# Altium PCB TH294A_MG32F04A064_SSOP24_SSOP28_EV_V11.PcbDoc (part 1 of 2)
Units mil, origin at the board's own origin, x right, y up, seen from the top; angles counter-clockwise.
Board outline 4724.41 x 2637.8 mil, 2 copper layers (Top Layer, Bottom Layer); 130 components, 100 nets, 562 pads, 309 vias.
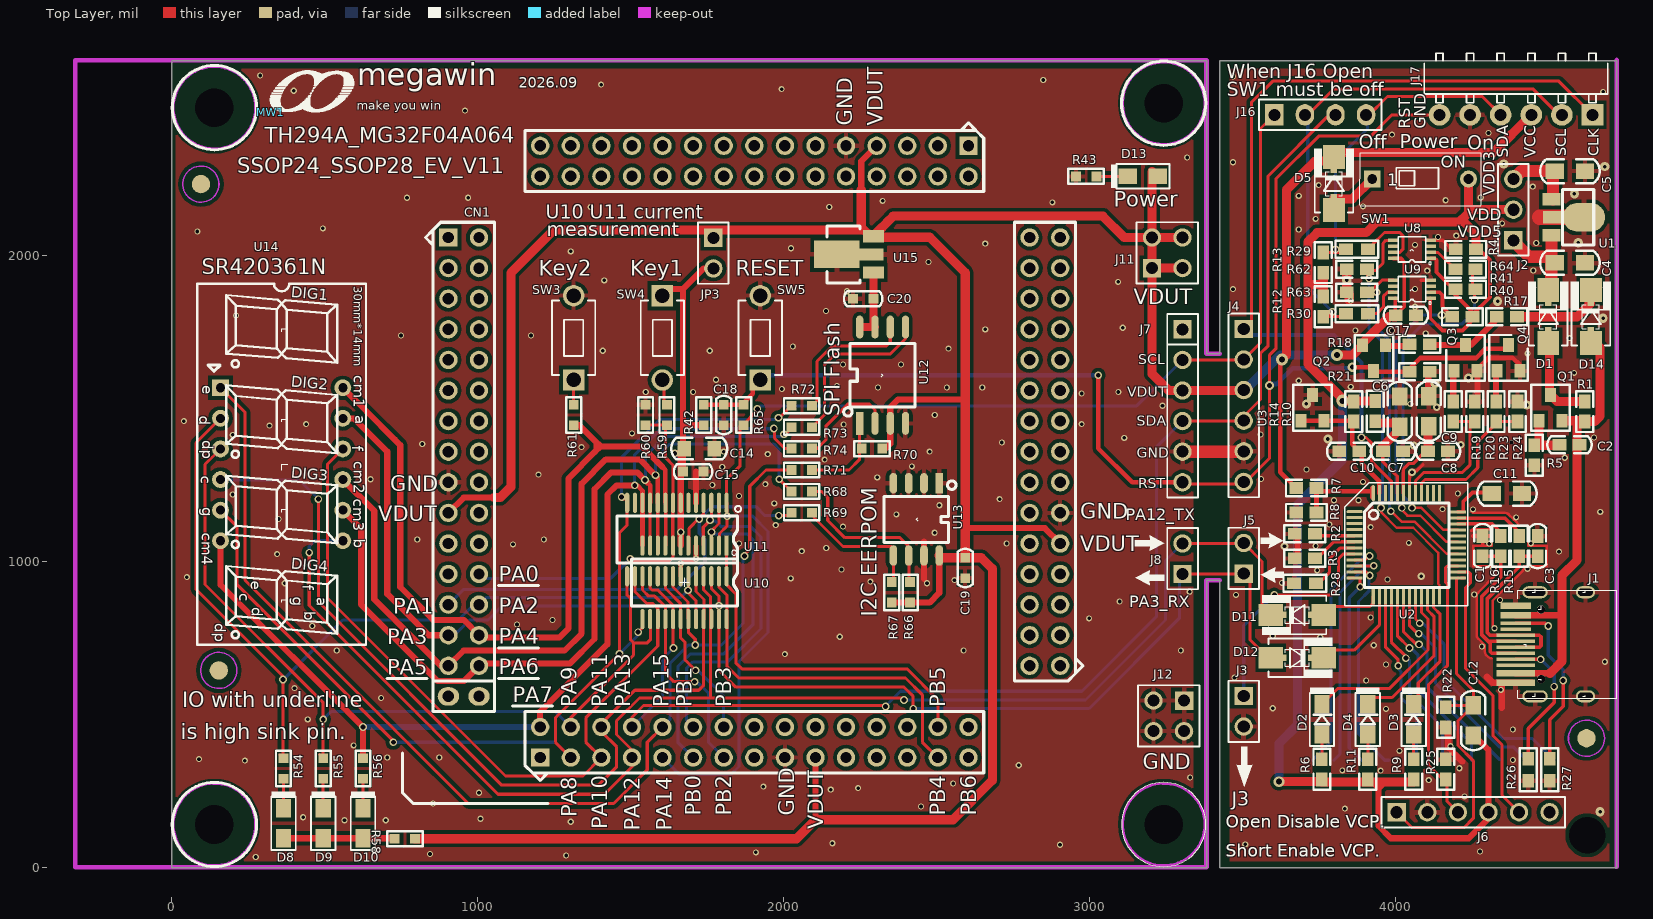
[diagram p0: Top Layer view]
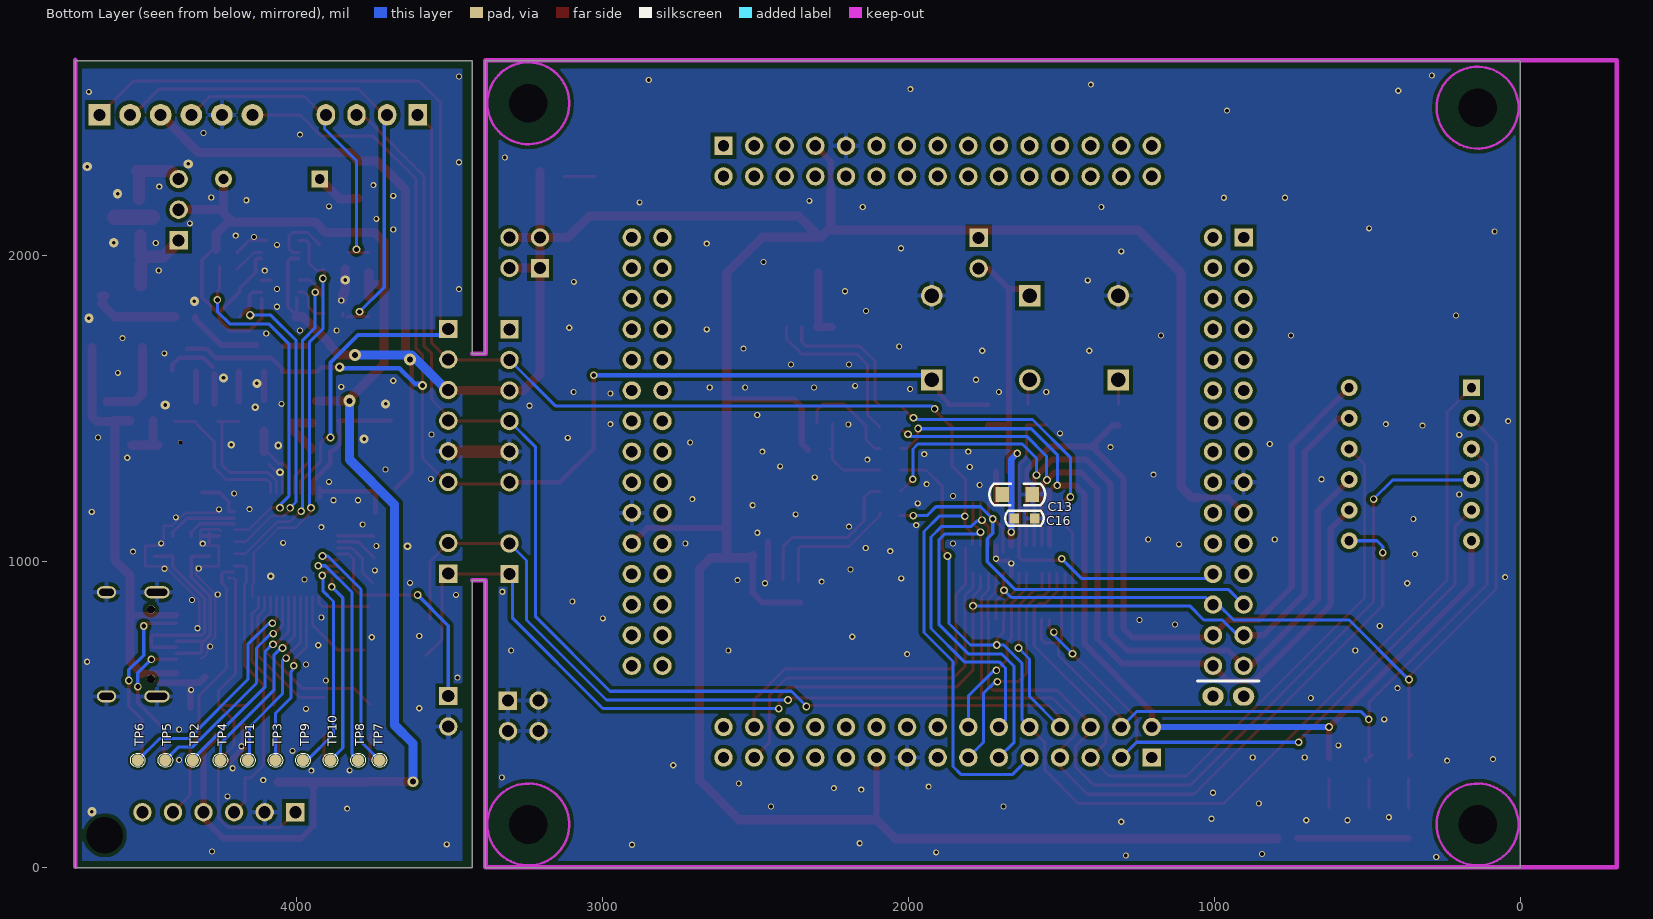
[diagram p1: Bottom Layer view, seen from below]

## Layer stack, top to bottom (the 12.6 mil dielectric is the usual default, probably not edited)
Top Layer: signal copper 1.4
Dielectric: dielectric 12.6, FR-4, Dk 4.8
Bottom Layer: signal copper 1.4

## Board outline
0,0 0,2637.8 3383.31,2637.8 3383.31,1680 3426.61,1680 3426.61,2637.8 4724.41,2637.8 4724.41,0 3426.61,0 3426.61,940 3383.31,940 3383.31,0

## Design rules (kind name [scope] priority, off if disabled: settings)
Clearance 12 [All] p1 off: gap=12
Clearance 7 [All] p2 off: gap=7
Clearance 6 [All] p3: gap=6
HoleSize 500-HoleSize [All] p1: absolutevalues=TRUE maxlimit=1500 minlimit=1 maxpercent=80.000 minpercent=20.000
PolygonConnect VIA [ISVIA] p1: connectstyle=Direct reliefconductorwidth=10 reliefentries=4 polygonreliefangle="90 Angle"
PolygonConnect "15 PolygonConnect" [All] p2: connectstyle=Relief reliefconductorwidth=15 reliefentries=4 polygonreliefangle="90 Angle"
RoomDefinition 2_MG32F04A064_SSOP28_V11 [InComponentClass('2_MG32F04A064_SSOP28_V11')] p1: confinementstyle=ConfineIn formatcopy=TRUE lockcomponents=FALSE outline 4960,2890 -205,2890 -205,-220 4960,-220
RoomDefinition 1_MLink_V14 [InComponentClass('1_MLink_V14')] p2: confinementstyle=ConfineIn formatcopy=TRUE lockcomponents=FALSE outline -100.59,-42.74 4792.92,-42.74 4792.92,2686.26 -100.59,2686.26
RoutingVias [All] p1: holewidth=16 width=25 viastyle="Through Hole" minholewidth=12 minwidth=25 maxholewidth=28 maxwidth=50
ShortCircuit [All] p1 off: allowed=FALSE
SilkscreenOverComponentPads [All] p1: minsilkscreentomaskgap=10
SolderMaskExpansion [All] p1: expansion=4
UnRoutedNet [All] p1 off:
Width [All] p1: maxlimit=100 minlimit=6 preferedwidth=8
24 further rules are at their usual default settings.

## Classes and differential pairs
component class 2_MG32F04A064_SSOP28_V11: C13 C14 C15 C16 C18 C19 C20 CN1 D8 D9 D10 D13 J7 J8 J11 J12 JP3 R42 R43 R54 R55 R56 R58 R59 R60 R61 R65 R66 R67 R68 R69 R70 R71 R72 R73 R74 SW3 SW4 SW5 U4 U10 U11 U12 U13 U14 U15
component class 1_MLink_V14: C1 C2 C3 C4 C5 C6 C7 C8 C9 C10 C11 C12 C17 D1 D2 D3 D4 D5 D11 D12 D14 J1 J2 J3 J4 J5 J6 J16 J17 MW1 Q1 Q2 Q3 Q4 R1 R2 R3 R4 R5 R6 R7 R8 R9 R10 R11 R12 R13 R14 R15 R16 R17 R18 R19 R20 R21 R22 R23 R24 R25 R26 R27 R28 R29 R30 R40 R41 R62 R63 R64 SW1 TP1 TP2 TP3 TP4 TP5 TP6 TP7 TP8 TP9 TP10 U1 U2 U3 U8 U9

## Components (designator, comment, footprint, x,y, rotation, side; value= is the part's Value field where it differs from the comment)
C1 "15pF" 0603C#1 4285.51,1051.26 r270 top
C2 "0.1uF" 0603C#1 4569.92,1382.52 r0 top
C3 "15pF" 0603C#1 4465.51,1051.26 r270 top
C4 "4.7uF" 0805C#1 4571.3,1977.2 r0 top
C5 "4.7uF" 0805C#1 4571.3,2277.2 r0 top
C6 "4.7uF" 0805C#1 4014.92,1491.26 r90 top
C7 "0.1uF" 0603C#1 3992.92,1361.26 r0 top
C8 "0.1uF" 0603C#1 4139.92,1361.26 r0 top
C9 "4.7uF" 0805C#1 4109.92,1492.52 r90 top
C10 "0.1uF" 0603C#1 3849.92,1361.26 r0 top
C11 "4.7uF" 0805C#1 4365.51,1223.16 r0 top
C12 "4.7uF" 0805C#1 4255.51,481.26 r90 top
C13 "4.7uF" 0805C#2 1645,1220 r180 bottom
C14 "4.7uF" 0805C#2 1725,1370 r180 top
C15 "0.1uF" 0603C#2 1705,1295 r180 top
C16 "0.1uF" 0603C#2 1621.5,1142 r180 bottom
C17 "0.1uF" 0603C#1 4034.92,1806.26 r180 top
C18 "NC" 0603C#2 1805,1480 r90 top
C19 "0.1uF" 0603C#2 2594.41,980 r270 top
C20 "0.1uF" 0603C#2 2260.91,1860 r0 top
CN1 "QFP122-CKT" QFP122-P2.54-CKT 1904.96,1360 r0 top locked
D1 "1N5817" DIODE_SMA_SOD323 4499.92,1801.26 r90 top
D2 "Yellow" 0805D 3760.51,484.52 r90 top
D3 "Green" 0805D 4060.51,484.52 r90 top
D4 "Red" 0805D 3910.51,484.52 r90 top
D5 "1N5817" DIODE_SMA_SOD323 3799.92,2236.26 r90 top
D8 "Red" 0805D 365.67,145.28 r90 top
D9 "Yellow" 0805D 495.67,145.28 r90 top
D10 "Green" 0805D 625.67,145.28 r90 top
D11 "1N5817" DIODE_SMA_SOD323 3679.96,826.26 r180 top
D12 "1N5817" DIODE_SMA_SOD323 3679.96,686.26 r0 top
D13 "Yellow" 0805D 3174.96,2260 r180 top
D14 "1N5817" DIODE_SMA_SOD323 4639.92,1801.26 r90 top
J1 "CJ-USB3-C16P" USB_CF_16_SMD 4429.2,730.38 r90 top
J2 "2&3 (0 ohm)" PS3P254 4386.34,2050.94 r90 top
J3 "VCP Option" PS2P254 3504.96,561.26 r270 top
J4 "OnBoard ICP/SWD Connector" PS6P254 3504.96,1761.26 r270 top
J5 "NC" PS2P254 3504.96,961.26 r90 top
J6 "CON6" PS6P254 4004.96,181.26 r0 top
J7 "CON6" PS6P254 3304.96,1760 r270 top locked
J8 "NC" PS2P254 3304.96,960 r90 top
J11 "CONN SOCKET 2x2/SM" PS2X2P254 3204.96,1960 r0 top
J12 "CONN SOCKET 2x2/SM" PS2X2P254 3309.92,546.26 r180 top
J16 "When J16 Open, SW1 must be off." PS4P254 3604.96,2461.26 r0 top
J17 "Off Board ICP/SWD Connector" PS6P254_90 4644.96,2461.26 r180 top locked
JP3 "JUMPER" PS2P254 1770.96,2059.08 r270 top
MW1 "MW-A4" MEGAWIN_3.4_1 324.41,2470 r0 top
Q1 "IRLML6402" SOT23 4507.46,1503.23 r0 top
Q2 "2N3906" SOT23 3930.42,1666.26 r180 top
Q3 "3904" SOT23_132 4229.96,1666.26 r0 top
Q4 "3904" SOT23_132 4369.96,1666.26 r0 top
R1 "NC" 0603R#1 4619.96,1491.26 r270 top
R2 "NC" 0603R#1 3704.96,1091.26 r0 top
R3 "NC" 0603R#1 3704.96,1011.26 r0 top
R4 "3.3K" 0603R#1 4230.92,2021.26 r0 top
R5 "1M" 0603R#1 4454.96,1348.26 r270 top
R6 "1K" 0603R#1 3760.51,321.52 r270 top
R7 "30K" 0603R#1 3709.92,1241.26 r180 top
R8 "10K" 0603R#1 3709.92,1161.26 r0 top
R9 "1K" 0603R#1 4060.51,321.52 r270 top
R10 "10" 0603R#1 3934.92,1492.52 r90 top
R11 "1K" 0603R#1 3910.51,321.52 r270 top
R12 "1.5K" 0603R#1 3764.92,1834.26 r90 top
R13 "1.5K" 0603R#1 3764.92,1978.26 r270 top
R14 "1K" 0603R#1 3864.92,1491.26 r270 top
R15 "30" 0603R#1 4405.51,1051.26 r90 top
R16 "30" 0603R#1 4345.51,1051.26 r90 top
R17 "4.7K" 0603R#1 4364.92,1801.26 r0 top
R18 "1K" 0603R#1 4079.96,1711.26 r0 top
R19 "4.7K" 0603R#1 4189.96,1491.26 r270 top
R20 "10K" 0603R#1 4259.96,1491.26 r270 top
R21 "1M" 0603R#1 4079.96,1621.26 r180 top
R22 "47K" 0603R#1 4165.51,491.26 r270 top
R23 "4.7K" 0603R#1 4329.96,1491.26 r270 top
R24 "10K" 0603R#1 4399.96,1491.26 r270 top
R25 "47K" 0603R#1 4165.51,321.26 r270 top
R26 "5.1K" 0603R#2 4434.96,320 r270 top
R27 "5.1K" 0603R#2 4504.96,320 r90 top
R28 "0" 0603R#2 3704.96,930 r180 top
R29 "100" 0603R#2 3874.92,2021.26 r0 top
R30 "100" 0603R#2 3874.92,1811.26 r0 top
R40 "NC" 0603R#1 4219.92,1801.26 r180 top
R41 "1.5K" 0603R#1 4229.92,1891.26 r0 top
R42 "47K" 0603R#3 1740,1480 r90 top
R43 "1K" 0603R#3 2989.96,2260 r0 top
R54 "470" 0603R#3 365.67,324.49 r270 top
R55 "470" 0603R#3 495.67,324.49 r270 top
R56 "470" 0603R#3 625.67,324.49 r270 top
R58 "0" 0603R#3 762.41,94.83 r0 top
R59 "1K" 0603R#3 1619.41,1480 r270 top
R60 "1M" 0603R#3 1549.41,1480 r90 top
R61 "1K" 0603R#3 1314.41,1480 r90 top
R62 "47k" 0603R#4 3874.92,1956.26 r0 top
R63 "47k" 0603R#4 3874.92,1881.26 r0 top
R64 "100" 0603R#4 4229.92,1956.26 r180 top
R65 "NC" 0603R#3 1870,1480 r90 top
R66 "4.7K" 0603R#3 2414.41,900 r270 top
R67 "4.7K" 0603R#3 2354.41,900 r270 top
R68 "NC" 0603R#3 2060,1230 r180 top
R69 "NC" 0603R#3 2060,1160 r180 top
R70 "10K" 0603R#3 2290,1370 r180 top
R71 "NC" 0603R#3 2060,1300 r180 top
R72 "NC" 0603R#3 2060,1510 r180 top
R73 "NC" 0603R#3 2060,1440 r180 top
R74 "NC" 0603R#3 2060,1370 r180 top
SW1 "SW KEY-SPST" DIP2_SW 3924.96,2251.26 r0 top
SW3 "Key2" SW_T_2P 1314.41,1732.2 r90 top
SW4 "Key1" SW_T_2P 1604.41,1732.2 r270 top
SW5 "NC" SW_T_2P 1924.41,1732.2 r90 top
TP1 "" PIN1_1H0 4159.96,351.26 r90 bottom
TP2 "" PIN1_1H0 4339.96,351.26 r90 bottom
TP3 "" PIN1_1H0 4069.96,351.26 r180 bottom
TP4 "" PIN1_1H0 4249.96,351.26 r180 bottom
TP5 "" PIN1_1H0 4429.96,351.26 r180 bottom
TP6 "" PIN1_1H0 4519.96,351.26 r180 bottom
TP7 "" PIN1_1H0 3729.96,351.26 r180 bottom
TP8 "" PIN1_1H0 3799.96,351.26 r180 bottom
TP9 "" PIN1_1H0 3979.96,351.26 r180 bottom
TP10 "" PIN1_1H0 3889.96,351.26 r90 bottom
U1 "AIC1734-33(SOT-89)" SOT89#1 4511.3,2126.26 r270 top
U2 "MG84FG516_LQFP48" LQFP48_7X7_050 4036.43,1055.65 r270 top locked
U3 "" SOT23 3729.92,1503.23 r0 top
U8 "SN74LVC2T45 (MSOP8_90P0.5)" MSOP8_90P0.5 4054.92,2021.26 r90 top
U9 "SN74LVC2T45 (MSOP8_90P0.5)" MSOP8_90P0.5 4054.92,1891.26 r90 top
U10 "MG32F04A064_SSOP24" SSOP24_150P0.635 1676.91,932.84 r180 top locked
U11 "MG32F04A064_SSOP28" SSOP28_150P0635 1651.91,1072.84 r180 top locked
U12 "MX25L3206E" SO8_208P127 2324.41,1610 r0 top locked
U13 "24LC02_MSOP8" SO8_150P127 2434.58,1138.74 r270 top
U14 "ARK-SR420361N" 7SEG_4A_12P254 359.92,1318.9 r270 top locked
U15 "AIC1734-33(SOT-89)" SOT89#2 2289.41,2005 r90 top

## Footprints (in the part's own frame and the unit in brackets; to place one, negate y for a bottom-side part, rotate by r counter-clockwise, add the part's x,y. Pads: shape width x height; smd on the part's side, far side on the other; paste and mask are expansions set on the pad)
7SEG_4A_12P254 [mil]
  rect 55x55 hole 30: 1(-250,-200)
  round 55 hole 30: 2(-150,-200) 3(-50,-200) 4(50,-200) 5(150,-200) 6(250,-200) 7(250,200) 8(150,200) 9(50,200) 10(-50,200) 11(-150,200) 12(-250,200)
  silkscreen extent -591,-276 591,276
0603C#1 [mil]
  rect 45x38 smd: 1(33,0) 2(-33,0)
  silkscreen extent -72,-28 72,28
0603C#2 [mil]
  rect 32x32 smd mask+4: 1(-33.5,0) 2(33.5,0)
  silkscreen extent -63,-24 63,24, body extent -30,-15 30,15, height 60
0603R#1 [mil]
  rect 45x38 smd: 1(33,0) 2(-33,0)
  silkscreen extent -67,-28 67,28
0603R#2 [mil]
  rect 45x38 smd: 1(-36,0) 2(36,0)
  silkscreen extent -70,-28 70,28
0603R#3 [mil]
  rect 32x32 smd mask+4: 1(-33.5,0) 2(33.5,0)
  silkscreen extent -58,-24 58,24, body extent -30,-15 30,15, height 60
0603R#4 [mil]
  rect 45x38 smd: 1(-33,0) 2(33,0)
  silkscreen extent -67,-28 67,28
0805C#1 [mil]
  rect 60x50 smd: 1(-49.21,0) 2(49.21,0)
  silkscreen extent -97,-39 97,39
0805C#2 [mil]
  rect 45x50 smd: 1(-49.21,0) 2(49.21,0)
  silkscreen extent -91,-35 91,35, body extent -40,-25 40,25, height 60
0805D [mil]
  rect 60x50 smd: 1(-49.21,0) 2(49.21,0)
  silkscreen extent -87,-40 104,40
DIODE_SMA_SOD323 [mm]
  rect 2x1.8 smd: 1(-2.2,0) 2(2.2,0)
  rect 0.95x0.54 smd: 1(-1.35,0) 2(1.35,0)
  silkscreen extent -2.4,-1.68 2.92,1.68
DIP2_SW [mm]
  rect 1.4x1.4 hole 0.8: 1(0,0)
  round 1.4 hole 0.8: 2(8,0)
  silkscreen extent -1.02,-2.2 9.02,2.2
LQFP48_7X7_050 [mm]
  oval 0.254x1.35 smd: 1(-2.75,-4.292)
  rect 0.254x1.35 smd: 2(-2.25,-4.292) 3(-1.75,-4.292) 4(-1.25,-4.292) 5(-0.75,-4.292) 6(-0.25,-4.292) 7(0.25,-4.292) 8(0.75,-4.292) 9(1.25,-4.292) 10(1.75,-4.292) 11(2.25,-4.292) 12(2.75,-4.292) 25(2.763,4.292) 26(2.263,4.292) 27(1.763,4.292) 28(1.263,4.292) 29(0.763,4.292) 30(0.263,4.292) 31(-0.237,4.292) 32(-0.737,4.292) 33(-1.237,4.292) 34(-1.737,4.292) 35(-2.237,4.292) 36(-2.737,4.292)
  rect 1.35x0.254 smd: 13(4.286,-2.744) 14(4.286,-2.244) 15(4.286,-1.744) 16(4.286,-1.244) 17(4.286,-0.744) 18(4.286,-0.244) 19(4.286,0.256) 20(4.286,0.756) 21(4.286,1.256) 22(4.286,1.756) 23(4.286,2.256) 24(4.286,2.756) 37(-4.286,2.756) 38(-4.286,2.256) 39(-4.286,1.756) 40(-4.286,1.256) 41(-4.286,0.756) 42(-4.286,0.256) 43(-4.286,-0.244) 44(-4.286,-0.744) 45(-4.286,-1.244) 46(-4.286,-1.744) 47(-4.286,-2.244)
  oval 1.35x0.254 smd: 48(-4.286,-2.744)
  silkscreen extent -5.15,-5.09 5.05,5.11
MEGAWIN_3.4_1 [mil]
  silkscreen extent -2,0 272,135
MSOP8_90P0.5 [mm]
  rect 0.3x0.85 smd: 1(-0.75,-1.55) 2(-0.25,-1.55) 3(0.25,-1.55) 4(0.75,-1.55) 5(0.75,1.55) 6(0.25,1.55) 7(-0.25,1.55) 8(-0.75,1.55)
  silkscreen extent -1.26,-1.61 1.05,1.14
PIN1_1H0 [mm]
  round 1 smd: 1(0,0)
  silkscreen extent -0.6,-0.6 0.6,0.6
PS2P254 [mil]
  rect 60x60 hole 39.37: 1(0,0)
  round 60 hole 39.37: 2(100,0)
  silkscreen extent -50,-50 150,50
PS2X2P254 [mil]
  rect 60x60 hole 39.37: 1(0,0)
  round 60 hole 39.37: 2(0,100) 3(100,0) 4(100,100)
  silkscreen extent -50,-50 150,150
PS3P254 [mil]
  rect 60x60 hole 39.37: 1(0,0)
  round 60 hole 39.37: 2(100,0) 3(200,0)
  silkscreen extent -50,-50 250,50
PS4P254 [mil]
  rect 60x70 hole 39.37: 1(0,0)
  oval 60x70 hole 39.37: 2(100,0) 3(200,0) 4(300,0)
  silkscreen extent -50,-50 350,50
PS6P254 [mil]
  rect 60x60 hole 39.37: 1(0,0)
  round 60 hole 39.37: 2(100,0) 3(200,0) 4(300,0) 5(400,0) 6(500,0)
  silkscreen extent -50,-50 550,50
PS6P254_90 [mm]
  rect 1.8x1.8 hole 1: 1(0,0)
  round 1.8 hole 1: 2(2.54,0) 3(5.08,0) 4(7.62,0) 5(10.16,0) 6(12.7,0)
  silkscreen extent -1.27,-5.11 13.97,-1
QFP122-P2.54-CKT [mil]
  rect 60x60 hole 37: 1(-700,-1000) 61(700,1000) 91(-1000,700)
  round 60 hole 37: 2(-700,-900) 3(-600,-1000) 4(-600,-900) 5(-500,-1000) 6(-500,-900) 7(-400,-1000) 8(-400,-900) 9(-300,-1000) 10(-300,-900) 11(-200,-1000) 12(-200,-900) 13(-100,-1000) 14(-100,-900) 15(0,-1000) 16(0,-900) 17(100,-1000) 18(100,-900) 19(200,-1000) 20(200,-900) 21(300,-1000) 22(300,-900) 23(400,-1000) 24(400,-900) 25(500,-1000) 26(500,-900) 27(600,-1000) 28(600,-900) 29(700,-1000) 30(700,-900) 31(1000,-700) 32(900,-700) 33(1000,-600) 34(900,-600) 35(1000,-500) 36(900,-500) 37(1000,-400) 38(900,-400) 39(1000,-300) 40(900,-300) 41(1000,-200) 42(900,-200) 43(1000,-100) 44(900,-100) 45(1000,0) 46(900,0) 47(1000,100) 48(900,100) 49(1000,200) 50(900,200) 51(1000,300) 52(900,300) 53(1000,400) 54(900,400) 55(1000,500) 56(900,500) 57(1000,600) 58(900,600) 59(1000,700) 60(900,700) 62(700,900) 63(600,1000) 64(600,900) 65(500,1000) 66(500,900) 67(400,1000) 68(400,900) 69(300,1000) 70(300,900) 71(200,1000) 72(200,900) 73(100,1000) 74(100,900) 75(0,1000) 76(0,900) 77(-100,1000) 78(-100,900) 79(-200,1000) 80(-200,900) 81(-300,1000) 82(-300,900) 83(-400,1000) 84(-400,900) 85(-500,1000) 86(-500,900) 87(-600,1000) 88(-600,900) 89(-700,1000) 90(-700,900) 92(-900,700) 93(-1000,600) 94(-900,600) 95(-1000,500) 96(-900,500) 97(-1000,400) 98(-900,400) 99(-1000,300) 100(-900,300) 101(-1000,200) 102(-900,200) 103(-1000,100) 104(-900,100) 105(-1000,0) 106(-900,0) 107(-1000,-100) 108(-900,-100) 109(-1000,-200) 110(-900,-200) 111(-1000,-300) 112(-900,-300) 113(-1000,-400) 114(-900,-400) 115(-1000,-500) 116(-900,-500) 117(-1000,-600) 118(-900,-600) 119(-1000,-700) 120(-900,-700)
  oval 70x60 hole 37: 121(-1000,-800) 122(-900,-800)
  silkscreen extent -1150,-1150 1075,1075
SO8_150P127 [mil]
  rect 67x25 smd: 1(-118.11,75)
  oval 67x25 smd: 2(-118.11,25) 3(-118.11,-25) 4(-118.11,-75) 5(118.11,-75) 6(118.11,-25) 7(118.11,25) 8(118.11,75)
  silkscreen extent -126,-105 75,130
SO8_208P127 [mm]
  rect 0.6x1.9 smd: 1(-1.905,-4)
  oval 0.6x1.9 smd: 2(-0.635,-4) 3(0.635,-4) 4(1.905,-4) 5(1.905,4) 6(0.635,4) 7(-0.635,4) 8(-1.905,4)
  silkscreen extent -3.23,-3.4 2.69,2.63
SOT23 [mil]
  rect 36x43.31 smd: 1(-37.5,-41.97) 2(37.5,-41.97)
  rect 36x46.06 smd: 3(0.5,41.97)
  silkscreen extent -63,-74 63,75
SOT23_132 [mil]
  rect 36x43.31 smd: 1(-37.5,-41.97) 3(37.5,-41.97)
  rect 36x46.06 smd: 2(0.5,41.97)
  silkscreen extent -63,-74 63,75
SOT89#1 [mm]
  rect 1.016x1.5 smd: 1(-1.5,0) 3(1.5,0)
  oval 2.4x3.5 smd: 2(0,2.7)
  rect 1.016x2.6 smd: 2(0,0.6)
  silkscreen extent -2.3,0.9 2.3,3.5
SOT89#2 [mm]
  rect 1.016x1.754 smd: 1(-1.5,-0.127) 3(1.5,-0.127)
  rect 2.286x3.754 smd: 2(0,2.921)
  rect 1.016x2.6 smd: 2(0,0.346)
  silkscreen extent -2.36,1 2.36,3.72
SSOP24_150P0.635 [mil]
  rect 13x66 smd: 1(-137.5,-120)
  oval 13x66 smd: 2(-112.5,-120) 3(-87.5,-120) 4(-62.5,-120) 5(-37.5,-120) 6(-12.5,-120) 7(12.5,-120) 8(37.5,-120) 9(62.5,-120) 10(87.5,-120) 11(112.5,-120) 12(137.5,-120) 13(137.5,120) 14(112.5,120) 15(87.5,120) 16(62.5,120) 17(37.5,120) 18(12.5,120) 19(-12.5,120) 20(-37.5,120) 21(-62.5,120) 22(-87.5,120) 23(-112.5,120) 24(-137.5,120)
  silkscreen extent -173,-105 173,77, body extent -175,-120 175,120, height 60
SSOP28_150P0635 [mil]
  oval 13.5x66 smd: 1(-162.5,-120) 2(-137.5,-120) 3(-112.5,-120) 4(-87.5,-120) 5(-62.5,-120) 6(-37.5,-120) 7(-12.5,-120) 8(12.5,-120) 9(37.5,-120) 10(62.5,-120) 11(87.5,-120) 12(112.5,-120) 13(137.5,-120) 14(162.5,-120) 15(162.5,120) 16(137.5,120) 17(112.5,120) 18(87.5,120) 19(62.5,120) 20(37.5,120) 21(12.5,120) 22(-12.5,120) 23(-37.5,120) 24(-62.5,120) 25(-87.5,120) 26(-112.5,120) 27(-137.5,120) 28(-162.5,120)
  silkscreen extent -210,-110 196,77, body extent -200,-120 200,120, height 60
SW_T_2P [mil]
  rect 70x70 hole 47.24: 1(-137.79,0)
  round 70 hole 47.24: 2(137.8,0)
  silkscreen extent -122,-71 122,71
USB_CF_16_SMD [mm]
  rect 0.55x3.2 smd: A1(-3.2,0.9) A4(-2.4,0.9)
  rect 0.3x3.2 smd: A5(-1.25,0.9) A6(-0.25,0.9) A7(0.25,0.9) B6(0.75,0.9) B7(-0.75,0.9) B8(-1.75,0.9)
  rect 0.3x2.54 smd: A8(1.25,0.9) B5(1.75,0.9)
  rect 0.55x2.54 smd: A9(2.4,0.9) A12(3.2,0.9)
  oval 1x2.1 hole 0.6 slot 1.7 at 90 deg: M1(-4.32,-0.718) M2(4.32,-0.718)
  oval 1x1.6 hole 0.6 slot 1.2 at 90 deg: M3(4.32,-4.898) M4(-4.32,-4.898)
  round 0.7 hole 0.7 unplated: M5(-2.89,-1.218) M6(2.89,-1.218)
  silkscreen extent -4.48,-7.5 4.55,0.74

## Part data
C1: library part "CAP NP_Dup1_C1"
C2: library part "CAP NP_C2"
C3: library part "CAP NP_Dup1_C3"
C4: library part "C NP_C4"
C5: library part "C NP_C5"
C6: library part CAP_C6
C7: library part "CAP NP_Dup1_C7"
C8: library part "CAP NP_C8"
C9: library part CAP_C9
C10: library part "CAP NP_C10"
C11: library part CAP_C11
C12: library part "CAP NP_Dup1_C12"
C13: library part "CAP NP_Dup1_C13"
C14: library part "CAP NP_Dup1_C14"
C15 C19 C20: library part "CAP NP_Dup1_C15"
C16: library part "CAP NP_Dup1_C16"
C17: library part "CAP NP_C17"
C18: library part "CAP NP_Dup1_C18"
CN1: library part QFP122-CKT_CN1
D1: library part "DIODE SCHOTTKY_D1"
D2: library part Led0_0_D2
D3: library part Led0_0_D3
D4: library part Led0_0_D4
D5: library part "DIODE SCHOTTKY_D5"
D8: library part LED_D8
D9: library part LED_D9
D10: library part LED_D10
D11: library part "DIODE SCHOTTKY_D11"
D12: library part "DIODE SCHOTTKY_D12"
D13: library part LED_D13
D14: library part "DIODE SCHOTTKY_D14"
J1: library part CJ-USB3-C16P_J1, "TPYE-C-9"
J2: library part CON3_J2
J3: library part CON2_J3
J4: library part CON6_J4
J5: library part CON2_J5
J6: library part CON6_J6
J7: library part CON6_Dup1_J7
J8: library part CON2_J8
J11: library part "CONN SOCKET 2x2/SM_J11"
J12: library part "CONN SOCKET 2x2/SM_J12"
J16: library part CON4_J16
J17: library part CON6_J17
JP3: library part JUMPER_JP3
MW1: library part MW_A4_2
Q1: library part "MOSFET P GSD_Q1"
Q2: library part 2N3906_0_Q2
Q3: library part "NPN BCE_Q3"
Q4: library part "NPN BCE_Q4"
R1: library part R_Dup4_R1
R2: library part R_Dup4_R2
R3: library part R_Dup4_R3
R4: library part R_Dup4_R4
R5: library part R_Dup2_R5
R6: library part R_Dup2_R6
R7: library part R_Dup2_R7
R8: library part R_Dup2_R8
R9: library part R_Dup2_R9
R10: library part R_Dup5_R10
R11: library part R_Dup2_R11
R12: library part R_Dup2_R12
R13: library part R_Dup2_R13
R14: library part R_Dup5_R14
R15: library part R_Dup5_R15
R16: library part R_Dup5_R16
R17: library part R_Dup2_R17
R18: library part R_Dup2_R18
R19: library part R_Dup2_R19
R20: library part R_Dup1_R20
R21: library part R_Dup1_R21
R22: library part R_Dup2_R22
R23: library part R_Dup2_R23
R24: library part R_Dup1_R24
R25: library part R_Dup2_R25
R26: library part R_Dup2_R26
R27: library part R_Dup2_R27
R28: library part R_Dup4_R28
R29: library part R_Dup2_R29
R30: library part R_Dup2_R30
R40: library part R_Dup3_R40
R41: library part R_Dup3_R41
R42 R65: library part R_Dup3_R42
R43 R66 R67 R68 R69 R70 R71 R72 R73 R74: library part R_Dup4_R43
R54: library part R_Dup4_R54
R55: library part R_Dup4_R55
R56: library part R_Dup4_R56
R58: library part R_Dup4_R58
R59: library part R_Dup3_R59
R60: library part R_Dup3_R60
R61: library part R_Dup3_R61
R62: library part R_Dup3_R62
R63: library part R_Dup3_R63
R64: library part R_R64
SW1: library part "SW KEY-SPST_SW1"
SW3 SW5: library part "SW TACT-SPST_SW3"
SW4: library part "SW TACT-SPST_SW4"
TP1: library part "T POINT A_TP1"
TP2: library part "T POINT A_TP2"
TP3: library part "T POINT A_TP3"
TP4: library part "T POINT A_TP4"
TP5: library part "T POINT A_TP5"
TP6: library part "T POINT A_TP6"
TP7: library part "T POINT A_TP7"
TP8: library part "T POINT A_TP8"
TP9: library part "T POINT A_TP9"
TP10: library part "T POINT A_TP10"
U1 U15: library part AIC1722-33_U1
U2: library part MG84FG516_LQFP48_U2
U3: library part TL431/CYL_U3
U8: library part SN74LVC2T45_U8
U9: library part SN74LVC2T45_U9
U13: library part 24LC64_MSOP8
U14: library part 7-segment_Common_Cathode

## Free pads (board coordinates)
  round 60 smd mask+39.37: 0(95.92,2234.68) 0(154.41,645) 0(4625.51,423.16)
  round 120 hole 125.98 unplated: 0(140,141.26) 0(140,2484.68) 0(3243.31,141.26) 0(3243.31,2499.06)
  round 100 hole 120 unplated: 0(4627.72,105.91)

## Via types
v1: diameter 20, hole 12, Top Layer to Bottom Layer, tented both sides, 221 vias
v2: diameter 25, hole 16, Top Layer to Bottom Layer, tented both sides, 61 vias
v3: diameter 30, hole 12, Top Layer to Bottom Layer, tented both sides, 13 vias
v4: diameter 25, hole 12, Top Layer to Bottom Layer, tented both sides, 6 vias
v5: diameter 40, hole 20, Top Layer to Bottom Layer, tented both sides, 3 vias
v6: diameter 30, hole 16, Top Layer to Bottom Layer, tented both sides, 2 vias
v7: diameter 15, hole 12, Top Layer to Bottom Layer, tented both sides, 1 vias
v8: diameter 35, hole 20, Top Layer to Bottom Layer, tented both sides, 1 vias
v9: diameter 28, hole 16, Top Layer to Bottom Layer, tented both sides, 1 vias

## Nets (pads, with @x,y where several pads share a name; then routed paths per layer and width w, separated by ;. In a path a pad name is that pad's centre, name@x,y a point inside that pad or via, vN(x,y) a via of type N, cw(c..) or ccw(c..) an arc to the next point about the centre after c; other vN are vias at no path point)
2.495V: C10.1 R14.1 U2.47 U3.1 U3.2 | length 442.3
  Top Layer w15: U3.1@3692.42,1461.26 U3.2@3767.42,1461.26 R14.1@3864.92,1461.26 ; R14.1@3859.92,1453.26 3859.92,1384.26 C10.1@3882.92,1361.26 3890.51,1361.26 3890.51,1320.71 3948.1,1263.12 U2.47@3948.1,1224.39
516P24: TP7.1 U2.9 | length 807.9
  Top Layer w10: U2.9@3867.44,1006.44 3901.4,1006.44 v2@3914.96,1020
  Bottom Layer w10: TP7.1@3729.96,351.26 3789.96,411.26 3789.96,910 3898.96,1019 v2(3915.96,1019)
516P25: TP8.1 U2.10 | length 765.6
  Top Layer w10: U2.10@3867.44,986.75 v2@3929.96,986.75
  Bottom Layer w10: TP8.1@3799.96,351.26 3819.96,371.26 3819.96,900 3906.96,987 v2(3929.96,987)
516P26: TP9.1 U2.11 | length 719.6
  Top Layer w10: U2.11@3867.44,967.07 3904.96,967.07 v2@3914.96,957.07
  Bottom Layer w10: v2@3914.96,955 3914.96,905 3879.96,870 3879.96,437.21 3965.91,351.26 TP9.1@3979.96,351.26
  other v2: 3916.96,955
516P27: TP10.1 U2.12 | length 651.8
  Top Layer w10: U2.12@3847.07,947.38 U2.12@3867.44,947.38 ; v2@3884.96,912.77 3884.96,918 U2.12@3884.96,946
  Bottom Layer w10: v2(3885.96,918) 3849.96,882 3849.96,391.26 TP10.1@3889.96,351.26
516P32: TP3.1 U2.15 | length 550.9
  Top Layer w10: U2.15@3967.78,886.91 3967.78,722.18 4009.96,680 v2@4009.96,670
  Bottom Layer w10: 4014.96,645 4018.54,641.42 4018.54,556.42 4069.96,505 TP3.1@4069.96,351.26
  other v2: 4009.96,660
516P33: TP1.1 U2.16 | length 664
  Top Layer w10: U2.16@3987.47,886.91 3987.47,737.49 v2@4037.46,687.5 ; v2@4039.46,689.5 v2@4041.96,687
  Bottom Layer w10: v2@4034.96,690 4037.46,687.5 4046.82,678.14 4046.82,568.14 ; 4046.82,620 4046.82,568.14 ; TP1.1@4154.96,351.26 4154.96,460 4046.82,568.14
  other v2: 4034.96,685
516P34: TP4.1 U2.17 | length 635.3
  Top Layer w10: U2.17@4007.15,886.91 4007.15,757.81 v2(4046.64,718.32)
  Bottom Layer w10: v2@4050.56,719.06 4075.11,694.52 4075.11,579.85 4249.96,405 TP4.1@4249.96,351.26
516P35: TP2.1 U2.18 | length 668.2
  Top Layer w10: U2.18@4026.84,886.91 4026.84,772.12 4073.46,725.5 v2@4074.96,724
  Bottom Layer w10: v2@4079.96,730 4103.39,706.57 4103.39,591.57 TP2.1@4341.83,353.13
  other v2: 4077.96,730
516P36: TP5.1 U2.19 | length 736.6
  Top Layer w10: U2.19@4046.52,886.91 4046.52,792.44 v2@4075.46,763.5
  Bottom Layer w10: v2(4076.96,765) 4084.96,765 4131.68,718.28 4131.68,603.28 4339.96,395 4386.22,395 TP5.1@4429.96,351.26 TP5.1@4420.51,351.26
516P37: TP6.1 U2.20 | length 795.9
  Top Layer w10: U2.20@4066.21,886.91 4066.21,812.75 v2(4079.96,799)
  Bottom Layer w10: v2(4079.96,799) 4090.96,799 4159.96,730 4159.96,615 4352.96,422 4449.22,422 TP6.1@4519.96,351.26 TP6.1@4510.51,351.26
CHIP_VDD: C13.1 C14.2 C15.2 C16.1 JP3.2 R42.1 SW4.1 U10.7 U11.7 | length 1460.9
  Top Layer w20: SW4.1@1612.91,1891.5 1671.5,1891.5 ; v2@1650,1355 C14.2@1664.41,1355 ; U10.7@1664.41,1052.84 v2(1664.41,1097) U11.7@1664.41,1192.84 1664.41,1295 1664.41,1354.31 C14.2@1664.41,1355 ; C14.2@1670.81,1354.31 C14.2@1671.5,1355 ; C15.2@1671.5,1295 C14.2@1671.5,1355 ; C14.2@1673.81,1355 C14.2@1671.5,1355 ; 1675,1446.5 R42.1@1740,1446.5 ; 1686.38,1906.38 1671.5,1891.5 ; JP3.2@1770.96,1959.08 1739.08,1959.08 1671.5,1891.5 ; C14.2@1664.41,1355 C14.2@1671.5,1355 ; C14.2@1671.5,1355 1671.5,1370 1671.5,1891.5
  Bottom Layer w20: v2(1645,1354.31) 1664.41,1334.9 1664.41,1220 1663.94,1141.95 1663.82,1121.31 v2@1663.82,1097
D+: C3.1 J1.A6 J1.B6 R15.2 | length 648.6
  Top Layer w12: J1.A6@4393.76,720.53 4472.29,720.53 4477.02,725.26 4477.02,754.26 4471.37,759.9 J1.B6@4393.76,759.9 4309.87,759.9 4301.51,768.26 4301.51,879.8 4405.51,983.8 R15.2@4405.51,1018.26 C3.1@4465.51,1018.26
D-: C1.1 J1.A7 J1.B7 R16.2 | length 590.1
  Top Layer w12: C1.1@4285.51,1018.26 R16.2@4345.51,1018.26 4345.51,949.26 4283.51,887.26 4283.51,760.8 4309.67,734.65 ; 4305.51,740.22 4315.92,740.22 ; 4310.51,735.49 4310.51,706.49 4316.15,700.85 J1.B7@4393.76,700.85 ; 4310.86,735.16 4315.92,740.22 ; J1.A7@4393.76,740.22 4315.92,740.22
DET_VDUT: R7.2 R8.1 U2.48 | length 292.1
  Top Layer w15: R8.1@3742.92,1161.26 R7.2@3742.92,1241.26 3752.92,1231.26 3920.9,1231.26 ; U2.48@3924.96,1211.26 3924.96,1224.39 U2.48@3924.96,1241.26
DUT_CLK: J4.1 J17.1 U2.45 | length 2846.5
  Top Layer w10: J4.1@3504.96,1761.26 3529.96,1786.26 3529.96,2501.3 3599.92,2571.26 4534.96,2571.26 J17.1@4644.96,2461.26 ; v2(3889.92,1406.26) 3904.92,1406.26 3921.92,1389.26 3921.92,1329.18 3987.47,1263.63 U2.45@3987.47,1224.39
  Bottom Layer w12: J4.1@3504.96,1761.26 3509.96,1761.26 3529.96,1741.26 3799.92,1741.26 3889.92,1651.26 v2(3889.92,1406.26)
DUT_RST: C18.2 J4.6 J7.6 J17.6 Q2.3 Q4.2 R21.1 R42.2 R65.2 SW5.1 | length 4676.5
  Top Layer w10: J7.6@3305.96,1254 3504.96,1254 3508.59,1257.63 3588.71,1337.75 v6(3588.71,1576.26) 3588.71,1675.05 3609.96,1696.3 3609.96,2251.3 3749.92,2391.26 3919.92,2391.26 3989.92,2461.26 J17.6@4144.96,2461.26
  Top Layer w15: R42.2@1740,1513.5 C18.2@1805,1513.5 R65.2@1870,1513.5 1870,1520 1900,1550 SW5.1@1900,1590.91 ; v2(3029.41,1610) 3029.41,1370.55 3139.96,1260 J7.6@3304.96,1260 ; v6(3859.92,1636.26) 3917.95,1636.26 Q2.3@3929.92,1624.29 ; Q2.3@3937.95,1621.26 R21.1@4046.96,1621.26 4046.96,1630.82 4082.4,1666.26 4264.92,1666.26 4294.92,1696.26 Q4.2@4360.55,1696.26
  Bottom Layer w15: SW5.1@1924.41,1594.41 SW5.1@1938.82,1580 ; SW5.1@1938.82,1610 2080,1610 ; 1988.82,1610 2080,1610 ; v2(3029.41,1610) 2080,1610 ; v6(3588.71,1576.26) 3588.71,1581.26 3612.92,1581.26 3664.92,1633.26 v6@3859.92,1633.26
DUT_SCL: J16.2 J17.2 R12.2 R30.1 | length 1704.6
  Top Layer w10: J16.2@3704.96,2461.26 3714.92,2461.26 3799.92,2546.26 4449.92,2546.26 J17.2@4534.92,2461.26 ; R12.2@3764.92,1801.26 3794.92,1801.26 R30.1@3833.23,1801.26 ; R12.2@3779.92,1817.26 3780.42,1816.76 3787.42,1809.76 3794.92,1802.26 ; R30.1@3834.92,1799.57 R30.1@3834.92,1801.26 ; R30.1@3849.92,1801.26 3849.92,1811.26 R30.1@3849.92,1813.95 ; J17.2@4519.92,2461.26 J17.2@4534.92,2461.26 ; J17.2@4539.94,2466.28 J17.2@4544.96,2461.26 J17.2@4534.92,2461.26
  Bottom Layer w10: J16.2@3714.22,2452 3714.22,1897.96 v2(3794.92,1817.26)
DUT_SDA: J16.4 J17.4 R13.2 R29.1 | length 1034.3
  Top Layer w10: R13.2@3764.92,2011.26 3804.92,2011.26 R29.1@3828.92,2011.26 ; J16.4@3909.94,2456.28 3974.92,2521.26 4284.96,2521.26 J17.4@4344.96,2461.26
  Bottom Layer w10: v2@3804.92,2016.26 v2(3804.92,2021.26) 3804.92,2311.26 3909.94,2416.28 J16.4@3909.94,2456.28
FAIL: D4.2 U2.22 | length 476
  Top Layer w10: D4.2@3910.51,556.26 3990.06,556.26 4127.28,693.48 4127.28,820.85 4105.58,842.54 U2.22@4105.58,886.91
GND_POWER: C1.2 C3.2 C4.2 C5.2 C6.2 C7.1 C8.1 C9.2 C10.2 C11.2 C13.2 C14.1 C15.1 C16.2 C17.2 C18.1 C19.2 C20.1 CN1.17 CN1.41 CN1.69 CN1.107 J1.A1 J1.A12 J1.M1 J1.M2 J1.M3 J1.M4 J3.2 J4.5 J6.2 J7.5 J12.1 J12.2 J12.3 J12.4 J17.5 Q3.3 Q4.3 R2.2 R3.2 R4.2 R5.1 R8.2 R20.2 R21.2 R22.1 R24.2 R25.2 R26.2 R27.1 R28.2 R43.1 R60.2 R62.1 R63.1 SW3.2 SW5.2 U1.2 U2.42 U3.3 U8.4 U9.4 U10.5 U11.5 U11.22 U12.4 U13.1 U13.2 U13.3 U13.4 U13.7 U15.2 | length 3398.4
  Top Layer w8: 4249,1101.05 4255,1107.05 4285.51,1107.05 4310.68,1107.05 4315.51,1102.22 4315.51,1059.26 4315.51,1051.76 4307.51,1051.76 4255.51,1051.76 4255.51,984.76 4320.51,984.76 4328.51,984.76 4328.51,978.26 4328.51,956.3 4271.49,899.28 ; v1@4249.51,1165.26 4255.04,1159.73 4359.04,1159.73 ; 4271.49,748.78 cw(c4283.51,760.8) 4266.51,760.8 ; 4271.51,899.26 ccw(c4283.53,887.24) 4266.53,887.24 4266.51,760.8 ; 4304.13,688.83 ccw(c4316.15,700.85) 4316.15,683.85 cw(c4316.15,700.85) 4304.12,688.85 4298.51,694.45 ; v1(4324.51,782.9) 4318.51,788.9 4318.51,872.76 4417.51,971.76 ccw(c4405.51,983.8) 4422.51,983.8 cw(c4405.51,983.8) 4417.53,971.78 ; 4422.51,984.76 4432.51,984.76 4495.51,984.76 4495.51,1051.76 4443.51,1051.76 4435.51,1051.76 4435.51,1060.26 4435.51,1117.76 4408.05,1117.76 4388.03,1137.78 4371.08,1154.73 ; 4266.51,760.8 ccw(c4283.51,760.8) 4271.51,748.76 4290.26,730.01 4293.51,726.76 4293.51,723.26 4293.51,706.49 ; 4293.51,706.49 ccw(c4310.51,706.49) 4298.51,694.45 ; 4293.51,706.49 ccw(c4310.51,706.49) 4298.49,694.47 ; 4359.04,1159.73 cw(c4359.04,1142.73) 4371.08,1154.73 ; 4359.04,1159.73 cw(c4359.04,1142.73) 4371.06,1154.75
  Top Layer w10: U2.42@4046.52,1224.39 4046.52,1284.86 v4(4054.92,1293.26) 4058.92,1297.26 4070.92,1297.26 4090.92,1317.26
  Top Layer w12: 4084.92,1920.79 U9.4@4115.94,1920.79 ; U8.4@4100.94,2050.79 U8.4@4115.94,2050.79 4139.92,2050.79 4155.39,2050.79 4191.42,2014.76 R4.2@4194.92,2011.26 ; 4253.51,1084.26 C1.2@4285.51,1084.26 C1.2@4286.51,1084.26 ; 4286.51,1055.26 C1.2@4286.51,1084.26 ; C1.2@4286.51,1092.26 C1.2@4286.51,1084.26 ; 4313.51,1084.26 C1.2@4286.51,1084.26
  Top Layer w15: U11.22@1664.41,952.84 1664.41,992.84 1665.49,993.92 1674.41,1002.84 1704.41,1002.84 1712.99,1011.42 1714.41,1012.84 U10.5@1714.41,1052.84 ; Q3.3@4275.21,1636.55 4306.16,1667.5 4383.62,1667.5 4407.46,1643.66 Q4.3@4407.46,1624.29
  Top Layer w20: U11.5@1714.41,1192.84 1714.41,1295 ; 2460,943.18 2460,1020.63 2460,1065.63 ; R3.2@3680.96,1011.26 3680.96,1091.26 R2.2@3680.96,1091.35 ; C9.2@4106.96,1529.26 4106.96,1541.73 4106.96,1583.26 R21.2@4106.96,1621.26 ; R22.1@4173.51,462.26 4173.51,458.26 4173.51,397 4173.51,393.15 4175.31,391.35 4188.96,377.7 4220,346.66 ; R20.2@4268.96,1516.26 4268.96,1524.26 Q3.3@4268.96,1613.79
  Top Layer w22: 4300.51,623.16 4319.3,604.38 J1.A1@4393.76,604.38 J1.A1@4445.51,604.38 ; 4348.4,524.05 4348.4,581.26 J1.A1@4348.4,598.51
  Top Layer w30: R63.1@3841.92,1881.26 v3(3841.92,1921.26) R62.1@3841.92,1956.26 ; v1@3849.92,1856.26 R63.1@3849.92,1876.26
  Top Layer w40: J7.5@3304.96,1360 J4.5@3504.96,1360
  Top Layer w50: 4471.74,2126.26 U1.2@4534.92,2126.26 U1.2@4596.3,2126.26
  other v1: 275,35 1290,40 845,45 1910,50 4277.51,53.16 2904.41,75 3509.86,76.26 2160,80 1305,150 565,155 700,155 1010,160 430,165 3835.51,193.16 1690,200 2450,200 855,210 4226.51,233.16 1005,245 2155,255 2244.41,260 1934.41,265 2555,275 4109.86,286.26 3329.86,295 3952.51,317.26 3827.51,318.26 4209.86,325 2769.41,335 239.41,350 4384.92,351.9 89.41,355 705,360 875,360 4013.96,381.9 4180.96,397 595,400 4384.92,451.9 445,485 3969.86,519.26 3599.86,521.26 685,555 4345.51,581.26 402,587 3904.96,611.9 3474.96,621.26 3969.86,664 4685.51,673.16 2005,698 540,710 2589.41,710 3299.41,710 4283.51,723.26 3929.86,727 3754.96,753.16 2184.41,755 3599.86,757.26 460,790 1129.41,795 1245,810 2999.41,815 3919.86,818 3099.41,870 4342.51,875.26 3479.92,891.9 4258.51,893.16 3327.96,901.9 370,930 2469.41,930 3629.86,931.26 2284.41,935 2559.41,940 3974.92,941.9 2024,946 50,950 3744.92,971.9 2190,975 4432.51,977.26 4320.51,978.26 1664.41,995 1714.41,1010 345,1025 4535.51,1033.16 2060,1035 2140,1045 3739.92,1051.9 1116,1057 4307.51,1059.26 1855,1060 2730,1060 4443.51,1060.26 4044.92,1061.9 803,1073 1217,1073 2494.41,1095 3919.96,1113.16 2195,1115 1975,1120 3784.92,1121.9 350,1140 4395.51,1145.26 2369.41,1155 4670.51,1163.16 4254.51,1171.26 4154.92,1172.26 2510,1185 1970,1191 3799.86,1201.26 3879.86,1201.26 2707,1205 1855,1215 200,1220 4204.96,1223.16 1768,1251 1941,1254 3894.96,1261.26 650,1270 3561.92,1270.52 2307,1276 1199.41,1285 3709.92,1301.9 1800,1310 2420,1312 2135,1334 4554.51,1340.26 1949,1352 1805,1360 2478,1360 1340,1375 819.41,1385 2714.41,1390 3114.41,1405 4649.86,1406.26 200,1415 3559.86,1416.26 1505,1420 320,1445 2197,1449 440,1450 2975,1450 40,1460 2495,1480 3239.41,1510 4049.86,1516.26 2975,1550 1550,1555 1705,1555 3095,1555 1995,1565 2309.41,1570 2534.41,1570 2650,1570 3854.92,1571.9 2175,1575 3684.92,1591.9 1780,1595 4584.92,1617.52 2195,1645 2384.41,1645 4432.95,1681.26 1409.41,1690 1759.41,1690 2540,1697 2031,1704 4569.86,1731.26 750,1740 1175,1740 4099.92,1746.26 3869.86,1756.26 3989.92,1756.26 2660,1760 3109.41,1765 210.31,1805 2139.41,1820 4064.92,1833.82 3854.92,1854.26 2207.91,1884.31 3469.86,1891.26 4064.92,1891.9 3094.41,1915 1414.41,1920 4104.92,1951.9 4451.3,1952.2 2474.41,1980 1305,2015 2025,2025 4064.86,2036.26 2660,2040 4461.24,2042.2 4139.92,2061.9 4199.86,2066.26 84.41,2080 3684.92,2086.26 494.41,2090 4349.86,2106.26 3739.86,2121.26 1370,2160 2150,2160 3894.92,2161.9 2879.41,2175 2324.41,2180 4164.92,2181.9 769.41,2190 969.41,2190 4279.86,2190.85 3684.92,2196.26 4449.86,2226.26 3749.86,2231.26 3469.86,2306.26 3319.96,2321.9 3989.86,2396.26 4304.92,2401.9 959.41,2475 4679.86,2536.26 399.41,2540 1994.41,2545 1404.41,2560 2849.41,2575 3469.86,2586.26 289.41,2590
  other v3: 4669.96,183.16 3779.92,1401.26 4429.92,1512.52 3709.86,1516.26 4130.51,1583.26 4239.86,1601.26 4679.86,1796.26 4334.92,1851.9 4598.34,2042.85 4585.89,2202.94 4684.92,2291.9 4354.92,2300.94
  other v4: 4085.51,953.26 3638.03,1051.26 4060.51,1380.26 4214.92,1382.52 4135.92,1505.26
  other v7: 4380.51,1390.26
I2C_SCL: R66.1 R68.1 U13.6 | length 544.8
  Top Layer w10: R68.1@2093.5,1230 2125,1230 2145,1210 2145,1135 2201,1079 2381,1079 2409.58,1050.42 U13.6@2409.58,1020.63 ; R66.1@2410.91,940 U13.6@2410.91,1020.63
I2C_SDA: R67.1 R69.1 U13.5 | length 424.8
  Top Layer w10: R69.1@2093.5,1160 2093.5,1151.5 2195,1050 2355,1050 2359.58,1045.42 U13.5@2359.58,1020.63 ; R67.1@2359.58,933.5 U13.5@2359.58,1015
ICP/SWD_SCL: R40.1 U2.31 U9.2 | length 1093
  Top Layer w8: v2@4021.92,1169.26 4039.92,1151.26 4081.92,1151.26 4168.19,1064.99 U2.31@4205.42,1064.99
  Top Layer w12: U9.2@4115.94,1881.42 4144.76,1881.42 4154.92,1871.26 4154.92,1833.26 R40.1@4186.92,1801.26
  Bottom Layer w10: v2(4021.92,1176.26) 4002.92,1195.26 4002.92,1724.26 4084.92,1806.26 v9(4152.99,1806.26)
